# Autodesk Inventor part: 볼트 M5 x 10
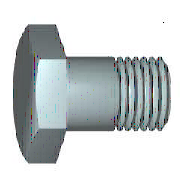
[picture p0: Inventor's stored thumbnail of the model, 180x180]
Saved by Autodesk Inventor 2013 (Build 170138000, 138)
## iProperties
IsCustomPart: 1
Created: 2012-02
Part Number: 볼트 M5 x 10
Material: 강철, 연강
Description: 6각 머리 볼트 및 6각 머리 나사
Document SubType Name: Modeling
Standard: KS B 1002
Designer: mduedu
Standards Organization: KS
Language: ko-KR
Size Designation: C  M 5 x 10
Categories: <MemberInstance><Categories><Category DisplayName="조임쇠" InternalName="e4da775c-781d-43d5-af7c-5136215cf5a6" Mnemonic="FSTN"><Category DisplayName="볼트" InternalN
Density: 1 g/cm^3
Author: mduedu
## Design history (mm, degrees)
sketch "스케치1"
  geometry: L1 (0, 2.5)-(10, 2.5); L2 (10, 2.5)-(10, 0); L3 (10, 0)-(0, 0); L4 (-2, 0)-(12, 0) reference; L5 (0, -0.5)-(0, 3) reference; L6 (0, 2.5)-(0, 0)
  constraints: 8 end point, 3 point on line, 1 collinear
  dimensions: "d2" = 5 diameter of L1 L3 (= GD); "d59" = 10 distance between parallel lines of L2 L5 (= NLG)
revolve "본체" sketch "스케치1" stored, may be unused: angle "d12" = 90 deg
sketch "스케치2"
  geometry: L1 (0, 4.619)-(4, 2.309); L2 (4, 2.309)-(4, -2.309); L3 (4, -2.309)-(0, -4.619); L4 (0, -4.619)-(-4, -2.309); L5 (-4, -2.309)-(-4, 2.309); L6 (-4, 2.309)-(0, 4.619); L7 (-5.6, 0)-(5.6, 0) reference; L8 (0, 6.466)-(0, -6.466) reference; 2 further points
  constraints: 12 end point, 2 midpoint, 1 coincident, 1 vertical, 11 other
  dimensions: "d11" = 8 distance between parallel lines of L5 L2 (= SW)
extrude "머리" join sketch "스케치2" distance "d3" = 3.5 (= KOH); taper "d4" = 0 deg
revolve "모따기1" stored, may be unused: angle "d21" = 90 deg
workplane "Work Plane1"
body "Solid1"
feature "스레드" dims "d15" = 7.6 (= GEL), "d16" = 0
chamfer "모따기2" distance "d6" = 0.49076 (= -0.5 x SPD + 0.5 x GD); stored, may be unused: second distance "d7" = 0.49086 (computed from GUL), angle "d55" = 45 deg
sketch "스케치4"
  geometry: L1 (-3.038, 4.8)-(-3.5, 4); L2 (-1.1, 0)-(-0.234, 0); L3 (-4.153, 0)-(0.419, 0) reference; L4 (-3.5, 4.8)-(-3.038, 4.8); L5 (-3.5, 4)-(-3.5, 4.8); L6 (0, 5.76)-(0, -0.96) reference
  constraints: 8 end point, 1 parallel, 1 perpendicular, 1 point on line
  dimensions: "d65" = 8 diameter of L1.end L2 (= SW); "d67" = 30 deg angle of L1 L5 (= ANG1); "d68" = 9.6 diameter of L4 L2 (= 1.2 x SW); "d69" = 3.5 distance between parallel lines of L5 L6 (= KOH)
other parameters: "NLG" = 10 [user parameter; used in 1 equation term], "GD" = 5 (= NND) [user parameter; used in 2 equation terms], "BDM" = 5 (= NND) [user parameter], "KOH" = 3.5 [user parameter; used in 2 equation terms], "GEL" = 7.6 [user parameter; used in 1 equation term], "SW" = 8 [user parameter; used in 5 equation terms], "SW0" = 8 (= SW) [user parameter], "SPD" = 4.01848 (= NND - 1.2269 x PTC) [user parameter; used in 1 equation term], "SD2" = 5 (= NND) [user parameter], "SD" = 0 [user parameter], "ANG1" = 30 deg [user parameter; used in 1 equation term], "GAL" = 0.49076 (= 0.61345 x PTC) [user parameter], "GUL" = 0.49076 (= 0.61345 x PTC) [user parameter; used in 1 equation term], "d8" = 0, "RR" = 0.2 [user parameter], "d58" = 0, "RR1" = 0.1 [user parameter], "TPU" = 12.5 (computed from PTC) [user parameter], "GD1" = 4.01848 (= THREADDIA - 1.2269 x PTC) [user parameter], "THREADDIA" = 5 [user parameter; used in 1 equation term], "TOA" = 30 deg [user parameter], "PTC" = 0.8 [user parameter; used in 5 equation terms], "NND" = 5 [user parameter; used in 4 equation terms], "E0" = 9.24 (= 1.155 x SW) [user parameter]
